(* Logix 5000 project; controller CompactLogix vendor 1 type 14 code 65 rev 16.20; software revision 16.03 *)

TASK MainTask (continuous, watchdog 500 ms) : MainProgram

MODULES
   Controller : vendor 1 type 14 code 65 (CompactLogixL35Controller 0, rev 16.20)
      LocalENB : 1769-L35E Ethernet Port (CompactLogixL35Ethernet 1, rev 16.3)
      Local : CompactBus (CompactVirtualAdapter 3, rev 16.1, Input RPI 2 ms)
         DPM : 1769-MODULE (Compact 1, rev 1.1, Output RPI 2 ms)
END_MODULES

TYPE DDLM_GLOBAL_CONTROL_CONFIRM :
STRUCT
   Reserved1 : INT;
   Reserved2 : INT;
   Answer : SINT;
   Failure : SINT;
   Reserved3 : INT;
   DeviceAdr : SINT;
END_STRUCT
END_TYPE

TYPE DDLM_GLOBAL_CONTROL_REQUEST :
STRUCT
   Reserved1 : INT;
   Reserved2 : INT;
   Reserved3 : INT;
   Command : SINT;
   Reserved4 : SINT;
   DeviceAdr : SINT;
   ConrolCommand : SINT;
   GroupSelect : SINT;
END_STRUCT
END_TYPE

TYPE DDLM_SET_PARAMETER_CONFIRM :
STRUCT
   Reserved1 : INT;
   Reserved2 : INT;
   Answer : SINT;
   Failure : SINT;
   Reserved3 : INT;
   DeviceAdr : SINT;
END_STRUCT
END_TYPE

TYPE DDLM_SET_PARAMETER_REQUEST :
STRUCT
   Reserved1 : INT;
   Reserved2 : INT;
   Reserved3 : INT;
   Command : SINT;
   Reserved4 : SINT;
   UsrPrm : SINT[234];
END_STRUCT
END_TYPE

TYPE DDLM_SLAVE_DIAGNOSTIC_CONFIRM :
STRUCT
   Reserved1 : INT;
   Reserved2 : INT;
   Answer : SINT;
   Failure : SINT;
   Reserved3 : INT;
   DeviceAdr : SINT;
   DataArea : SINT;
   DataAdr : INT;
   DataIdx : SINT;
   DataCnt : SINT;
   DataType : SINT;
   Function : SINT;
   StationState_1 : SINT;
   StationState_2 : SINT;
   StationState_3 : SINT;
   MasterAddress : SINT;
   IdentNumber : INT;
   Reserved4 : INT;
   ExtDiag : SINT[100];
END_STRUCT
END_TYPE

TYPE DDLM_SLAVE_DIAGNOSTIC_REQUEST :
STRUCT
   Reserved1 : INT;
   Reserved2 : INT;
   Reserved3 : INT;
   Command : SINT;
   Reserved4 : SINT;
   DeviceAdr : SINT;
   DataArea : SINT;
   DataAdr : INT;
   DataIdx : SINT;
   DataCnt : SINT;
   DataType : SINT;
   Function : SINT;
END_STRUCT
END_TYPE

TYPE DPM_DEV_COMMAND_REGISTER :   // Device Command Register
STRUCT
   Reserved0 : BOOL;   // Reserved
   Reserved1 : BOOL;   // Reserved
   Reserved2 : BOOL;   // Reserved
   Reserved3 : BOOL;   // Reserved
   Reserved4 : BOOL;   // Reserved
   NRdy : BOOL;   // Application Not Ready
   Init : BOOL;   // Init ( Warm boot )
   Reset : BOOL;   // Reset ( Cold boot )
   HsReq0 : BOOL;   // Slave Diag Request
   HsReq1 : BOOL;   // Global Control Request
   HsReq2 : BOOL;   // Reserved
   HsReq3 : BOOL;   // Reserved
   HsReq4 : BOOL;   // Reserved
   HsReq5 : BOOL;   // Reserved
   HsReq6 : BOOL;   // Reserved
   HsReq7 : BOOL;   // Reserved
   Reserved5 : SINT;   // Reserved
   Reserved6 : SINT;   // Reserved
END_STRUCT
END_TYPE

TYPE DPM_DEV_STATUS_REGISTER :   // Device Status Register
STRUCT
   Reserved0 : BOOL;
   Reserved1 : BOOL;
   Reserved2 : BOOL;
   Reserved3 : BOOL;
   Reserved4 : BOOL;
   Com : BOOL;   // Communication
   Run : BOOL;   // Running
   Rdy : BOOL;   // Ready
   HsAck0 : BOOL;   // Slave Diag Acknowledge
   HsAck1 : BOOL;   // Global Control Acknowledge
   HsAck2 : BOOL;
   HsAck3 : BOOL;
   HsAck4 : BOOL;
   HsAck5 : BOOL;
   HsAck6 : BOOL;
   HsAck7 : BOOL;
   Reserved5 : SINT;
   Reserved6 : SINT;
END_STRUCT
END_TYPE

TYPE DPM_DPV1_ALARM_INDICATION :   // DPV1 Alarm Indication
STRUCT
   AlarmIndication : BOOL;   // Indicates an alarm
   Reserved1 : BOOL;
   Reserved2 : BOOL;
   Reserved3 : BOOL;
   Reserved4 : BOOL;
   Reserved5 : BOOL;
   Reserved6 : BOOL;
   AlarmOverrun : BOOL;   // Overflow of the modules internal alarm buffer
   AlarmCnt : SINT;   // Alarm indication counter
   RemoteAddress : SINT;   // Address of Slave with Alarm
   Slot : SINT;   // Slot Number
   Sequence : SINT;   // Sequence Number
   AlarmType : SINT;   // Alarm Type
   AlarmSpec : SINT;   // Alarm Specification
   Reserved7 : SINT;
END_STRUCT
END_TYPE

TYPE DPM_FW_REVISION :   // Firmware Major/Minor Revision
STRUCT
   FwMinor : SINT;   // Firmware Minor Revison
   FwMajor : SINT;   // Firmware Major Revison
   Reserved : INT;   // Reserved
END_STRUCT
END_TYPE

TYPE DPM_GLOBAL_CONTROL_COMMAND :   // Global Control Command
STRUCT
   SlaveAddress : SINT;   // Slave Address
   ControlCommand : SINT;   // Control Command to be send
   GroupSelect : SINT;   // Group Select
   Reserved1 : SINT;
END_STRUCT
END_TYPE

TYPE DPM_GLOBAL_STATE_FIELD :   // PROFIBUS Master Global State Field
STRUCT
   Ctrl : BOOL;   // Control error
   Aclr : BOOL;   // Auto clear error
   Nexc : BOOL;   // Non exchange error
   Fat : BOOL;   // Fatal error
   Eve : BOOL;   // Event error
   NRdy : BOOL;   // Host not ready notification
   Tout : BOOL;   // Timeout
   Reserved1 : BOOL;   // Reserved
   DPM_State : SINT;   // Master main state
   Err_rem_adr : SINT;   // Faulty remote address
   Err_event : SINT;   // Error Number
   Bus_err_cnt : INT;   // Heavy bus error counter
   Time_out_cnt : INT;   // Number of rejected PROFIBUS Telegr.
   Reserved : SINT[8];   // Reserved
   Sl_cfg : BOOL[128];   // Slave Config
   Sl_state : BOOL[128];   // Slave State
   Sl_diag : BOOL[128];   // Slave Diag
END_STRUCT
END_TYPE

TYPE DPM_INPUT_ARRAY :
STRUCT
   DevStaReg : DPM_DEV_STATUS_REGISTER;
   FwRev : DPM_FW_REVISION;
   GlobStateField : DPM_GLOBAL_STATE_FIELD;
   SlaveDiag : DPM_SLAVE_DIAG_DATA;
   AlarmInd : DPM_DPV1_ALARM_INDICATION;
   InputData : SINT[408];   // PROFIBUS Input data.
END_STRUCT
END_TYPE

TYPE DPM_MODULEDEF :
STRUCT
   AlarmCnf : MSAL1M_ALARM_CONFIRM;
   AlarmIndCounter : SINT;
   AlarmReceiveCounter : INT;   // Alarm Counter
   AlarmResErr : BOOL;
   AlarmRsp : MSAL1M_ALARM_RESPONSE;
   DoDDLMGlblCtrl : BOOL;
   DoDDLMSetPrm : BOOL;
   DoDDLMSlaveDiag : BOOL;
   DoDPV1AlarmRsp : BOOL;
   DoDPV1ReadReq : BOOL;
   DoDPV1WriteReq : BOOL;
   DpmInputArray : DPM_INPUT_ARRAY;
   DpmOutputArray : DPM_OUTPUT_ARRAY;
   GlbCtrlCnf : DDLM_GLOBAL_CONTROL_CONFIRM;   // Global Control Confirmation
   GlbCtrlReq : DDLM_GLOBAL_CONTROL_REQUEST;   // Global Control Request
   MainInitDone : BOOL;
   ReadCnf : MSAC1_READ_CONFIRM;   // Read Confimation
   ReadReq : MSAC1_READ_REQUEST;   // Read Request
   SetPrmCnf : DDLM_SET_PARAMETER_CONFIRM;   // Set parameter confirmation
   SetPrmReq : DDLM_SET_PARAMETER_REQUEST;   // Set parameter request
   SlaveAddress : SINT;   // Slave address used by several CIP messages
   SlaveDiagCnf : DDLM_SLAVE_DIAGNOSTIC_CONFIRM;   // Slave Diag Confirmation
   SlaveDiagReq : DDLM_SLAVE_DIAGNOSTIC_REQUEST;   // Slave Diag Request
   WriteCnf : MSAC1_WRITE_CONFIRM;   // Slave Write Confirmation
   WriteReq : MSAC1_WRITE_REQUEST;   // Slave Write Request
END_STRUCT
END_TYPE

TYPE DPM_OUTPUT_ARRAY :
STRUCT
   DevCmdReg : DPM_DEV_COMMAND_REGISTER;
   DiagReqAdr : DPM_SLAVE_DIAG_COMMAND;
   GlobCtrl : DPM_GLOBAL_CONTROL_COMMAND;
   Reserved : SINT[4];
   OutputData : SINT[480];   // PROFIBUS Output data.
END_STRUCT
END_TYPE

TYPE DPM_SLAVE_DIAG_COMMAND :   // Requested address for SlaveDiagnostics
STRUCT
   SlaveAddress : SINT;
   DiagMode : SINT;
   Reserved1 : SINT;
   Reserved2 : SINT;
END_STRUCT
END_TYPE

TYPE DPM_SLAVE_DIAG_DATA :   // Slave standard diagnostic data according to PROFIBUS norm.
STRUCT
   SlaveAddress : SINT;   // Slave address
   DiagFailure : SINT;   // Slave Diag Failure
   Sta1_StationNotExist : BOOL;   // No response
   Sta1_StationNotReady : BOOL;   // Station not ready
   Sta1_CfgFault : BOOL;   // Configuration faulty
   Sta1_ExtDiag : BOOL;   // Extended diagnostic
   Sta1_NotSupp : BOOL;   // Sync,Freeze not supported
   Sta1_InvalidResponse : BOOL;   // Response faulty
   Sta1_PrmFault : BOOL;   // Parameters faulty
   Sta1_MasterLock : BOOL;   // Locked by a master
   Sta2_PrmReq : BOOL;   // Request new parameter
   Sta2_StatDiag : BOOL;   // Static diagnostic
   Sta2_Slave : BOOL;   // Set to 1 by a slave
   Sta2_Watchdog : BOOL;   // Watchdog ON/OFF
   Sta2_FreezeMode : BOOL;   // Freeze mode active
   Sta2_SyncMode : BOOL;   // Sync mode active
   Sta2_Reserved : BOOL;   // Reserved
   Sta2_Deactivated : BOOL;   // Slave deactivated
   Sta3_Reserved0 : BOOL;   // Reserved
   Sta3_Reserved1 : BOOL;   // Reserved
   Sta3_Reserved2 : BOOL;   // Reserved
   Sta3_Reserved3 : BOOL;   // Reserved
   Sta3_Reserved4 : BOOL;   // Reserved
   Sta3_Reserved5 : BOOL;   // Reserved
   Sta3_Reserved6 : BOOL;   // Reserved
   Sta3_ExtDiagOverflow : BOOL;   // Extended diagnostic overflow
   MasterAddress : SINT;   // Corresponding master address
   IdentNumber : INT;   // PROFIBUS Ident number
END_STRUCT
END_TYPE

TYPE MSAC1_READ_CONFIRM :   // DPV1 Read Confirmation
STRUCT
   Reserved1 : INT;
   Reserved2 : INT;
   Answer : SINT;
   Failure : SINT;
   Reserved3 : INT;
   DeciceAdr : SINT;
   DataArea : SINT;
   DataAdr : INT;
   DataIdx : SINT;
   DataCnt : SINT;
   DataType : SINT;
   Function : SINT;
   Data : SINT[240];
END_STRUCT
END_TYPE

TYPE MSAC1_READ_REQUEST :   // DPV1 Read Request
STRUCT
   Reserved1 : INT;
   Reserved2 : INT;
   Reserved3 : INT;
   Command : SINT;
   Reserved4 : SINT;
   DeviceAdr : SINT;
   DataArea : SINT;
   DataAdr : INT;
   DataIdx : SINT;
   DataCnt : SINT;
   DataType : SINT;
   Function : SINT;
END_STRUCT
END_TYPE

TYPE MSAC1_WRITE_CONFIRM :   // DPV1 Write Confirmation
STRUCT
   Reserved1 : INT;
   Reserved2 : INT;
   Answer : SINT;
   Failure : SINT;
   Reserved3 : INT;
   DeciceAdr : SINT;
   DataArea : SINT;
   DataAdr : INT;
   DataIdx : SINT;
   DataCnt : SINT;
   DataType : SINT;
   Function : SINT;
   ErrorCode1 : SINT;
   ErrorCode2 : SINT;
END_STRUCT
END_TYPE

TYPE MSAC1_WRITE_REQUEST :   // DPV1 Write Request
STRUCT
   Reserved1 : INT;
   Reserved2 : INT;
   Reserved3 : INT;
   Command : SINT;
   Reserved4 : SINT;
   DeviceAdr : SINT;
   DataArea : SINT;
   DataAdr : INT;
   DataIdx : SINT;
   DataCnt : SINT;
   DataType : SINT;
   Function : SINT;
   data : SINT[240];
END_STRUCT
END_TYPE

TYPE MSAL1M_ALARM_CONFIRM :
STRUCT
   Reserved1 : INT;
   Reserved2 : INT;
   Answer : SINT;
   Failure : SINT;
   Reserved3 : INT;
   SlaveAdr : SINT;
   SlotNum : SINT;
   SeqNum : SINT;
   AlarmType : SINT;
   AlarmSpec : SINT;
   Reserved4 : SINT;
END_STRUCT
END_TYPE

TYPE MSAL1M_ALARM_RESPONSE :
STRUCT
   Reserved1 : INT;
   Reserved2 : INT;
   Reserved3 : INT;
   Command : SINT;
   Reserved4 : SINT;
   SlaveAdr : SINT;
   SlotNum : SINT;
   SeqNum : SINT;
   AlarmType : SINT;
   AlarmSpec : SINT;
   Reserved5 : SINT;
END_STRUCT
END_TYPE

ADD_ON_INSTRUCTION AOIPS69DPM   (* revision 1.1 *)
// Add-On instruction for the PS69-DPM module
// Revision note:
// Added viewing capability for the Add_On Instruction
VAR_IN_OUT
   Connection_Input : INT[248]; {required}
   Connection_Output : INT[248]; {required}
   PS69DPM : DPM_MODULEDEF; {required}
   AlarmRspMsg : MESSAGE; {required}
   GlbCtrlMsg : MESSAGE; {required}
   ReadReqMsg : MESSAGE; {required}
   SetPrmReqMsg : MESSAGE; {required}
   SlaveDiagMsg : MESSAGE; {required}
   WriteReqMsg : MESSAGE; {required}
END_VAR

ROUTINE Logic   (* ladder *)
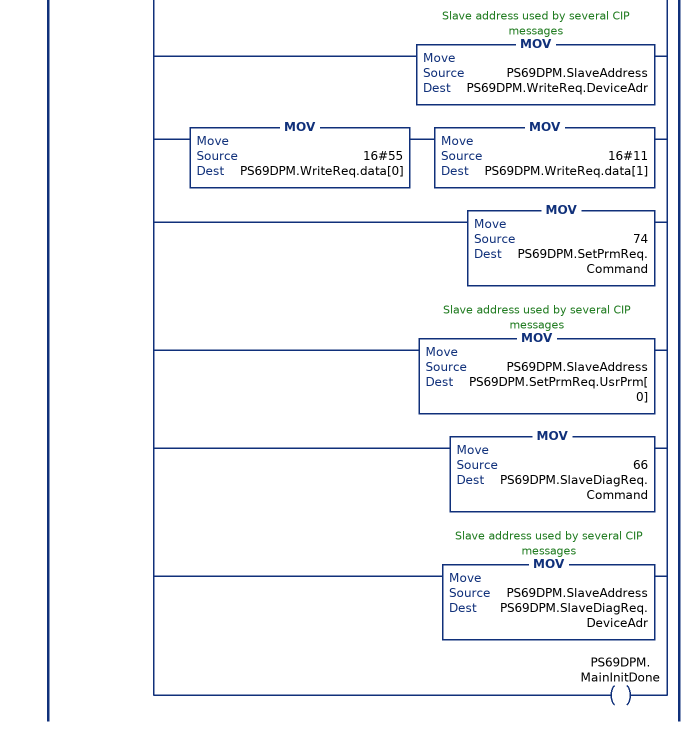
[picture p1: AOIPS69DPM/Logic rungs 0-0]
   // Vendor/Address/Phone/Product (revs) /Description/ACDname (date)
   // Prosoft Technology Inc
   // 1675 Chester Avenue, Fourth Floor
   // Bakersfield, CA 93301
   // USA
   // Phone: 1-661-7165100
   // PS69-DPM
   // PROFIBUS-DP Master Module
   // PS69_DPM_messaging_L32E.ACD (Rev1.0) (07/28/05)
   // Although this program has been developed with great care and intensively tested,
   // Prosoft Technology Inc cannot guarantee the suitability of this program
   // for any purpose not confirmed by us in writing.
   // We reserve the right to modify our products and their specifications at any time in as far as this contributes to technical progress.
   // The version of the manual supplied with the program applies.
   // Guarantee claims shall be limited to the right to require rectification. Liability for any damages which may have arisen from the use of this program or its documentation shall be limited to cases of intent.
   // This program is a basic example RSLogix5000 project used for sending PROFIBUS messages to the communication module "PS69-DPM". This project provides an example for every supported PROFIBUS message by the module.
   // For detailed information about the these messages (functionality, parameters, error codes etc. ) refer to the module User Manual.
   // Rung 0 calls all init routines for one time, to initialize the PROFIBUS commands.
   0: XIO(PS69DPM.MainInitDone)[MOV(18,PS69DPM.AlarmRsp.Command) ,MOV(70,PS69DPM.GlbCtrlReq.Command) ,MOV(PS69DPM.SlaveAddress,PS69DPM.GlbCtrlReq.DeviceAdr) ,MOV(17,PS69DPM.ReadReq.Command) ,MOV(1,PS69DPM.ReadReq.Function) ,MOV(PS69DPM.SlaveAddress,PS69DPM.ReadReq.DeviceAdr) ,MOV(10,PS69DPM.ReadReq.DataType) ,MOV(17,PS69DPM.WriteReq.Command) ,MOV(2,PS69DPM.WriteReq.Function) ,MOV(10,PS69DPM.WriteReq.DataType) ,MOV(PS69DPM.SlaveAddress,PS69DPM.WriteReq.DeviceAdr) ,MOV(16#55,PS69DPM.WriteReq.data[0]) MOV(16#11,PS69DPM.WriteReq.data[1]) ,MOV(74,PS69DPM.SetPrmReq.Command) ,MOV(PS69DPM.SlaveAddress,PS69DPM.SetPrmReq.UsrPrm[0]) ,MOV(66,PS69DPM.SlaveDiagReq.Command) ,MOV(PS69DPM.SlaveAddress,PS69DPM.SlaveDiagReq.DeviceAdr) ,OTE(PS69DPM.MainInitDone) ];
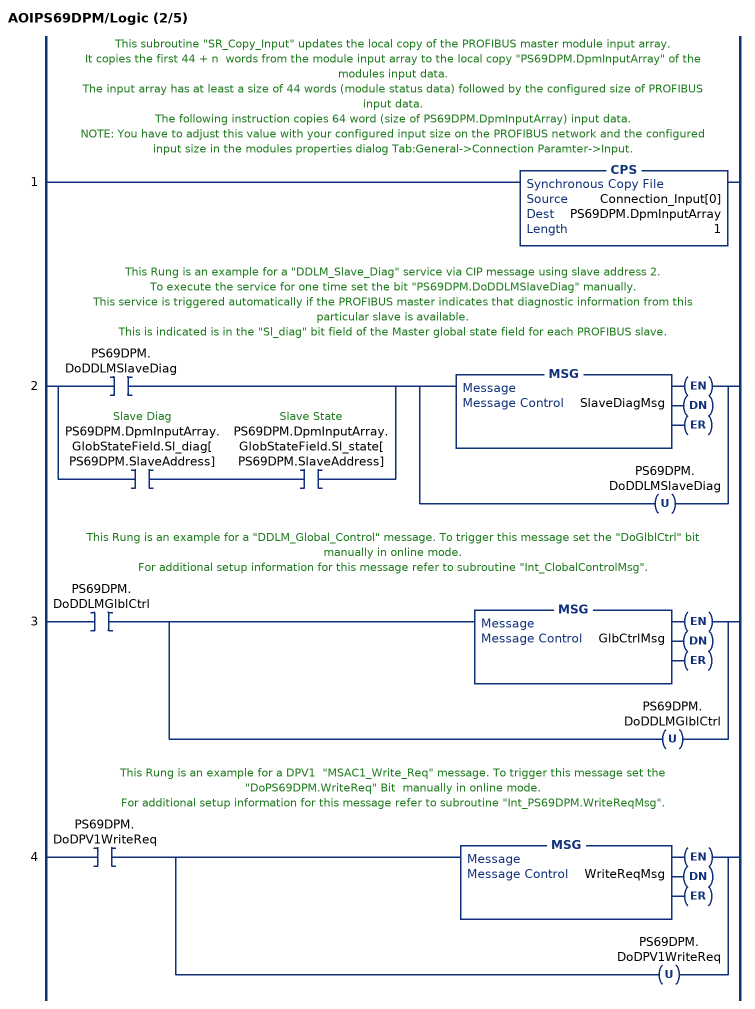
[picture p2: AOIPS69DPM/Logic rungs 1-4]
   // This subroutine "SR_Copy_Input" updates the local copy of the PROFIBUS master module input array.
   // It copies the first 44 + n  words from the module input array to the local copy "PS69DPM.DpmInputArray" of the modules input data.
   // The input array has at least a size of 44 words (module status data) followed by the configured size of PROFIBUS input data.
   // The following instruction copies 64 word (size of PS69DPM.DpmInputArray) input data.
   // NOTE: You have to adjust this value with your configured input size on the PROFIBUS network and the configured input size in the modules properties dialog Tab:General->Connection Paramter->Input.
   1: CPS(Connection_Input[0],PS69DPM.DpmInputArray,1);
   // This Rung is an example for a "DDLM_Slave_Diag" service via CIP message using slave address 2.
   // To execute the service for one time set the bit "PS69DPM.DoDDLMSlaveDiag" manually.
   // This service is triggered automatically if the PROFIBUS master indicates that diagnostic information from this particular slave is available.
   // This is indicated is in the "Sl_diag" bit field of the Master global state field for each PROFIBUS slave.
   2: [XIC(PS69DPM.DoDDLMSlaveDiag) ,XIC(PS69DPM.DpmInputArray.GlobStateField.Sl_diag[PS69DPM.SlaveAddress]) XIC(PS69DPM.DpmInputArray.GlobStateField.Sl_state[PS69DPM.SlaveAddress]) ][MSG(SlaveDiagMsg) ,OTU(PS69DPM.DoDDLMSlaveDiag) ];
   // This Rung is an example for a "DDLM_Global_Control" message. To trigger this message set the "DoGlblCtrl" bit  manually in online mode.
   // For additional setup information for this message refer to subroutine "Int_ClobalControlMsg".
   3: XIC(PS69DPM.DoDDLMGlblCtrl)[MSG(GlbCtrlMsg) ,OTU(PS69DPM.DoDDLMGlblCtrl) ];
   // This Rung is an example for a DPV1  "MSAC1_Write_Req" message. To trigger this message set the "DoPS69DPM.WriteReq" Bit  manually in online mode.
   // For additional setup information for this message refer to subroutine "Int_PS69DPM.WriteReqMsg".
   4: XIC(PS69DPM.DoDPV1WriteReq)[MSG(WriteReqMsg) ,OTU(PS69DPM.DoDPV1WriteReq) ];
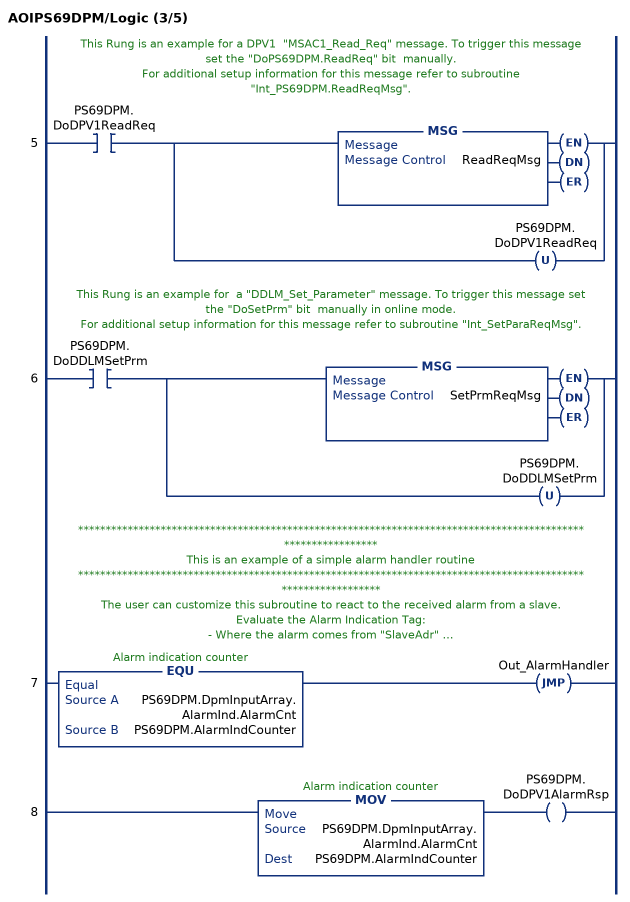
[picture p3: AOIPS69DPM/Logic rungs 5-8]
   // This Rung is an example for a DPV1  "MSAC1_Read_Req" message. To trigger this message set the "DoPS69DPM.ReadReq" bit  manually.
   // For additional setup information for this message refer to subroutine "Int_PS69DPM.ReadReqMsg".
   5: XIC(PS69DPM.DoDPV1ReadReq)[MSG(ReadReqMsg) ,OTU(PS69DPM.DoDPV1ReadReq) ];
   // This Rung is an example for  a "DDLM_Set_Parameter" message. To trigger this message set the "DoSetPrm" bit  manually in online mode.
   // For additional setup information for this message refer to subroutine "Int_SetParaReqMsg".
   6: XIC(PS69DPM.DoDDLMSetPrm)[MSG(SetPrmReqMsg) ,OTU(PS69DPM.DoDDLMSetPrm) ];
   // *************************************************************************************************************
   // This is an example of a simple alarm handler routine
   // **************************************************************************************************************
   // The user can customize this subroutine to react to the received alarm from a slave.
   // Evaluate the Alarm Indication Tag:
   //  - Where the alarm comes from "SlaveAdr" ?
   // -  What kind of alarm is it  "AlarmType" ?
   // ect. ....
   7: EQU(PS69DPM.DpmInputArray.AlarmInd.AlarmCnt,PS69DPM.AlarmIndCounter)JMP(Out_AlarmHandler);
   8: MOV(PS69DPM.DpmInputArray.AlarmInd.AlarmCnt,PS69DPM.AlarmIndCounter)OTE(PS69DPM.DoDPV1AlarmRsp);
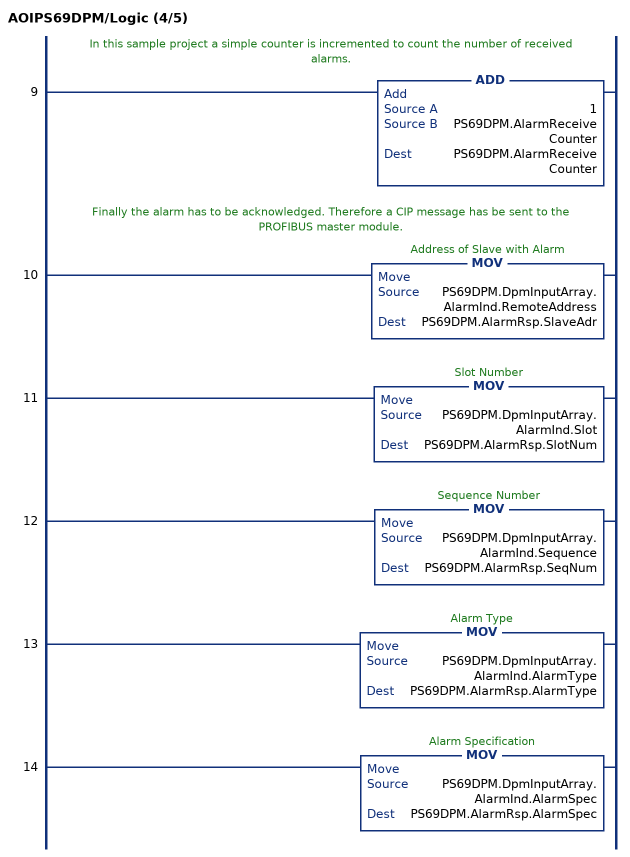
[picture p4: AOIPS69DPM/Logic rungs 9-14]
   // In this sample project a simple counter is incremented to count the number of received alarms.
   9: ADD(1,PS69DPM.AlarmReceiveCounter,PS69DPM.AlarmReceiveCounter);
   // Finally the alarm has to be acknowledged. Therefore a CIP message has be sent to the PROFIBUS master module.
   10: MOV(PS69DPM.DpmInputArray.AlarmInd.RemoteAddress,PS69DPM.AlarmRsp.SlaveAdr);
   11: MOV(PS69DPM.DpmInputArray.AlarmInd.Slot,PS69DPM.AlarmRsp.SlotNum);
   12: MOV(PS69DPM.DpmInputArray.AlarmInd.Sequence,PS69DPM.AlarmRsp.SeqNum);
   13: MOV(PS69DPM.DpmInputArray.AlarmInd.AlarmType,PS69DPM.AlarmRsp.AlarmType);
   14: MOV(PS69DPM.DpmInputArray.AlarmInd.AlarmSpec,PS69DPM.AlarmRsp.AlarmSpec);
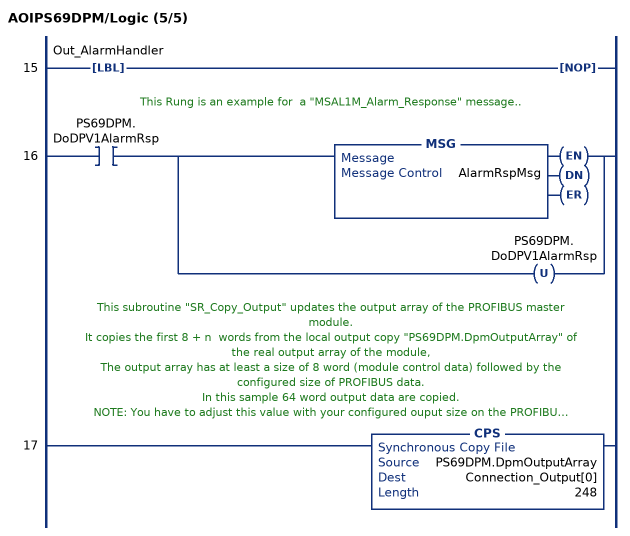
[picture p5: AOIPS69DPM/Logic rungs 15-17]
   15: LBL(Out_AlarmHandler)NOP();
   // This Rung is an example for  a "MSAL1M_Alarm_Response" message..
   16: XIC(PS69DPM.DoDPV1AlarmRsp)[MSG(AlarmRspMsg) ,OTU(PS69DPM.DoDPV1AlarmRsp) ];
   // This subroutine "SR_Copy_Output" updates the output array of the PROFIBUS master module.
   // It copies the first 8 + n  words from the local output copy "PS69DPM.DpmOutputArray" of the real output array of the module,
   // The output array has at least a size of 8 word (module control data) followed by the configured size of PROFIBUS data.
   // In this sample 64 word output data are copied.
   // NOTE: You have to adjust this value with your configured ouput size on the PROFIBUS network and the configured output size in the modules properties dialog Tab:General->Connection Paramter->Output.
   17: CPS(PS69DPM.DpmOutputArray,Connection_Output[0],248);
END_ROUTINE
END_ADD_ON_INSTRUCTION

VAR_GLOBAL   (* controller tags *)
   AlarmRspMsg : MESSAGE;   // Alarm Response Message
        MessageParameters(ServiceCode := 16#0064, LocalElement := PS69DPM.AlarmRsp, DestinationTag := PS69DPM.AlarmCnf, ...)
   AOIPS69DPM : AOIPS69DPM;
   Connection_Input : INT[248];
   Connection_Output : INT[248];
   GlbCtrlMsg : MESSAGE;   // Global Control Message
        MessageParameters(ServiceCode := 16#0064, LocalElement := PS69DPM.GlbCtrlReq, DestinationTag := PS69DPM.GlbCtrlCnf, ...)
   PS69DPM : DPM_MODULEDEF;
   ReadReqMsg : MESSAGE;   // Slave Read Request Message
        .EN   // Slave Read Request Message
        MessageParameters(ServiceCode := 16#0064, LocalElement := PS69DPM.ReadReq, DestinationTag := PS69DPM.ReadCnf, ...)
   SetPrmReqMsg : MESSAGE;
        MessageParameters(ServiceCode := 16#0064, LocalElement := PS69DPM.SetPrmReq, DestinationTag := PS69DPM.SetPrmCnf, ...)
   SlaveDiagMsg : MESSAGE;   // Slave Diag Message
        .EN   // Slave Diag Message
        MessageParameters(ServiceCode := 16#0064, LocalElement := PS69DPM.SlaveDiagReq, DestinationTag := PS69DPM.SlaveDiagCnf, ...)
   WriteReqMsg : MESSAGE;   // Slave Write Request Message
        .EN   // Slave Write Request Message
        MessageParameters(ServiceCode := 16#0064, LocalElement := PS69DPM.WriteReq, DestinationTag := PS69DPM.WriteCnf, ...)
END_VAR

PROGRAM MainProgram   (* main routine MainRoutine *)

ROUTINE MainRoutine   (* ladder *)
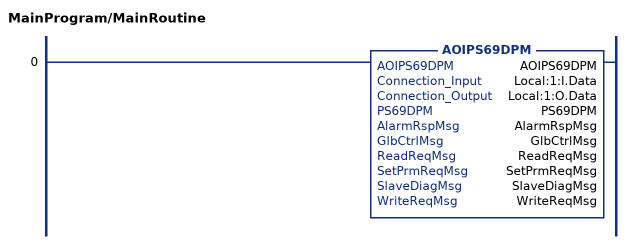
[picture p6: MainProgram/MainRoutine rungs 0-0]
   0: AOIPS69DPM(AOIPS69DPM,Local:1:I.Data,Local:1:O.Data,PS69DPM,AlarmRspMsg,GlbCtrlMsg,ReadReqMsg,SetPrmReqMsg,SlaveDiagMsg,WriteReqMsg);
END_ROUTINE
END_PROGRAM
